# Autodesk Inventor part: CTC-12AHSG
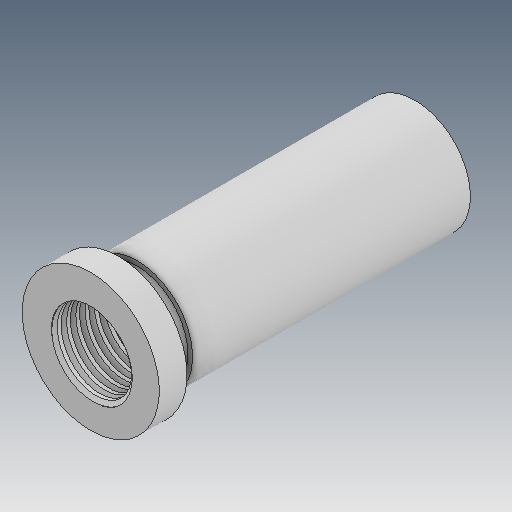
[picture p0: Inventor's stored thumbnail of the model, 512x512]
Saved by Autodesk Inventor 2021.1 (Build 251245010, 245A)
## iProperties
Created: 2010-01
Part Number: CTC-12AHSG
Material: Ogólny
Document SubType Name: Modeling
Designer: user
Density: 1 g/cm^3
Appearance: Domyślna
Author: user
Revision Number: 1LAST_VERSION
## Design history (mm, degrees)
feature "Baza1"
node "Bryła1"
